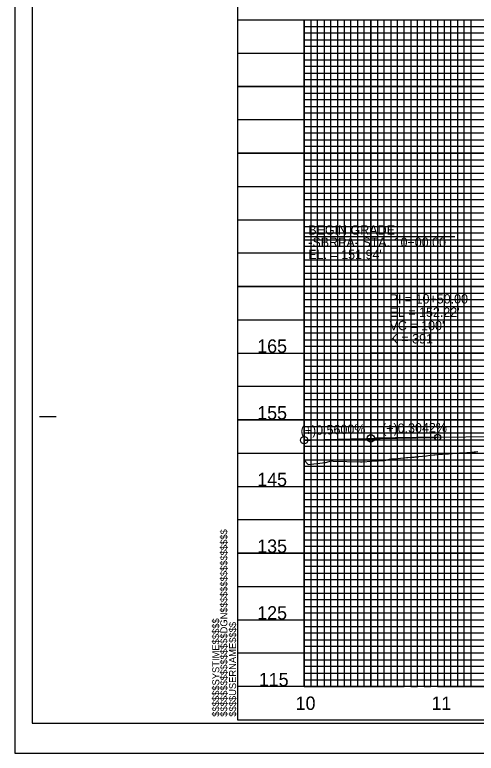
# Model space of a CAD drawing. Extents: x 573468 to 580768, y -57414 to -51768.
# Drawn here: x 578678 to 579024, y -57414 to -56860 of the extents above; entities that cross this region are included whole.
import ezdxf

# ---------------------------------------------------------------- set-up
doc = ezdxf.new("R2010")
doc.units = 0
for name, color, linetype in [('Exist Vertical Profile Ground Line', 7, 'Continuous'), ('Exist Vertical Profile Horizontal Axis Label Major', 7, 'Continuous'), ('Exist Vertical Profile Vertical Axis Label', 7, 'Continuous'), ('Prop Grid Mask', 7, 'Continuous'), ('Prop PFL Text', 7, 'Continuous'), ('Prop Vertical Profile Curve Label', 7, 'Continuous'), ('Prop Vertical Profile Grade', 7, 'Continuous'), ('Prop Vertical Profile Grade Label', 7, 'Continuous'), ('Prop VPI Label', 7, 'Continuous'), ('Sheet Cutting Line CELL', 7, 'Continuous'), ('Sheet DOT Grid CELL', 7, 'Continuous'), ('Sheet Layout Profile Border Port 2', 7, 'Continuous'), ('Sheet Plot Border Inside CELL', 7, 'Continuous'), ('Sheet Plot Border Outside CELL', 7, 'Continuous'), ('Sheet Profile CELL', 7, 'Continuous'), ('Sheet Profile Grid Major CELL', 7, 'Continuous'), ('Sheet Profile Grid Middle CELL', 7, 'Continuous'), ('Sheet Profile Grid Minor CELL', 7, 'Continuous')]:
    doc.layers.add(name, color=color, linetype=linetype)

msp = doc.modelspace()

# ---------------------------------------------------------------- linework, layer by layer
at = {"layer": 'Exist Vertical Profile Ground Line'}
msp.add_lwpolyline([(578895.21, -57193.93), (578898.19, -57197.05), (578911.11, -57195.47), (578915.67, -57194.34), (578916.92, -57194.57), (578937.43, -57195.09), (578938.61, -57195.11), (578945.89, -57194.47), (578948.08, -57194.36), (578950.84, -57194.22), (578953.61, -57194.09), (578955.14, -57194.02), (578956.37, -57193.76), (578959.14, -57193.17), (578960.91, -57192.8), (578961.9, -57192.71), (578964.67, -57192.46), (578967.44, -57192.22), (578970.2, -57191.99), (578971.95, -57191.84), (578972.97, -57191.78), (578975.73, -57191.61), (578977.55, -57191.51), (578978.5, -57191.42), (578980.65, -57191.21), (578981.26, -57191.14), (578984.03, -57190.81), (578986.79, -57190.5), (578989.56, -57190.19), (578992.32, -57189.88), (578993.03, -57189.81), (578995.09, -57189.57), (578995.4, -57189.54), (578997.85, -57189.38), (578998.82, -57189.29), (579000.62, -57189.17), (579003.39, -57188.99), (579006.15, -57188.81), (579008.92, -57188.64), (579010.26, -57188.55), (579011.68, -57188.44), (579014.45, -57188.22), (579017.21, -57188.01), (579019.98, -57187.81), (579022.74, -57187.61), (579023.6, -57187.55), (579025.51, -57187.41)], dxfattribs=at)
at = {"layer": 'Prop Grid Mask'}
msp.add_lwpolyline([(578945.21, -57063.55), (579045.21, -57063.55), (579045.21, -57113.55), (578945.21, -57113.55)], close=True, dxfattribs=at)
at = {"layer": 'Prop PFL Text'}
for q in [(579008.22, -57026.03), (578895.21, -57178.85)]:
    msp.add_line((578895.21, -57026.03), q, dxfattribs=at)
at = {"layer": 'Prop Vertical Profile Curve Label'}
msp.add_circle((578995.21, -57176.69), 2.25, dxfattribs=at)
at = {"layer": 'Prop Vertical Profile Grade'}
msp.add_line((578995.21, -57176.69), (579065.21, -57175.62), dxfattribs=at)
msp.add_spline([(578895.21, -57178.85), (578897.21, -57178.79), (578899.21, -57178.74), (578901.21, -57178.68), (578903.21, -57178.63), (578905.21, -57178.58), (578907.21, -57178.52), (578909.21, -57178.47), (578911.21, -57178.42), (578913.21, -57178.37), (578915.21, -57178.32), (578917.21, -57178.26), (578919.21, -57178.21), (578921.21, -57178.16), (578923.21, -57178.12), (578925.21, -57178.07), (578927.21, -57178.02), (578929.21, -57177.97), (578931.21, -57177.92), (578933.21, -57177.88), (578935.21, -57177.83), (578937.21, -57177.79), (578939.21, -57177.74), (578941.21, -57177.7), (578943.21, -57177.65), (578945.21, -57177.61), (578947.21, -57177.57), (578949.21, -57177.52), (578951.21, -57177.48), (578953.21, -57177.44), (578955.21, -57177.4), (578957.21, -57177.36), (578959.21, -57177.32), (578961.21, -57177.28), (578963.21, -57177.24), (578965.21, -57177.2), (578967.21, -57177.17), (578969.21, -57177.13), (578971.21, -57177.09), (578973.21, -57177.05), (578975.21, -57177.02), (578977.21, -57176.98), (578979.21, -57176.95), (578981.21, -57176.91), (578983.21, -57176.88), (578985.21, -57176.85), (578987.21, -57176.81), (578989.21, -57176.78), (578991.21, -57176.75), (578993.21, -57176.72), (578995.21, -57176.69)], degree=3, dxfattribs=at)
at = {"layer": 'Prop VPI Label'}
for p, q in [((578895.21, -57178.85), (578942.47, -57177.53)), ((578995.21, -57176.69), (578947.96, -57177.41))]:
    msp.add_line(p, q, dxfattribs=at)
for centre in [(578895.21, -57178.85), (578945.21, -57177.45)]:
    msp.add_circle(centre, 2.75, dxfattribs=at)
at = {"layer": 'Sheet Cutting Line CELL'}
for p, q in [((578678.21, -56313.55), (578678.21, -57413.55)), ((578678.21, -57413.55), (580362.21, -57413.55))]:
    msp.add_line(p, q, dxfattribs=at)
at = {"layer": 'Sheet DOT Grid CELL'}
for p, q in [((578845.21, -56863.55), (580345.1, -56863.55)), ((578895.21, -56863.55), (578895.21, -57363.55)), ((578945.21, -56863.55), (578945.21, -57363.55)), ((578995.21, -56863.55), (578995.21, -57363.55)), ((578845.21, -56913.55), (580345.1, -56913.55)), ((578845.21, -56963.55), (580345.1, -56963.55)), ((578845.21, -57013.55), (580345.1, -57013.55)), ((578845.21, -57063.55), (580345.1, -57063.55)), ((578845.21, -57113.55), (580345.1, -57113.55)), ((578845.21, -57163.55), (580345.1, -57163.55)), ((578845.21, -57213.55), (580345.1, -57213.55)), ((578845.21, -57263.55), (580345.1, -57263.55)), ((578845.21, -57313.55), (580345.1, -57313.55))]:
    msp.add_line(p, q, dxfattribs=at)
at = {"layer": 'Sheet Layout Profile Border Port 2'}
msp.add_lwpolyline([(578895.21, -56863.55), (580295.21, -56863.55), (580295.21, -57363.55), (578895.21, -57363.55)], close=True, dxfattribs=at)
at = {"layer": 'Sheet Plot Border Inside CELL'}
msp.add_lwpolyline([(578691.21, -57391.1), (580357.71, -57391.1), (580357.71, -56336), (578691.21, -56336)], close=True, dxfattribs=at)
at = {"layer": 'Sheet Plot Border Outside CELL'}
msp.add_lwpolyline([(578678.21, -57413.55), (580362.21, -57413.55), (580362.21, -56313.55), (578678.21, -56313.55)], close=True, dxfattribs=at)
at = {"layer": 'Sheet Profile CELL'}
for p, q in [((578845.21, -56863.55), (580345.21, -56863.55)), ((578696.71, -57161.05), (578709.21, -57161.05)), ((580345.21, -57363.55), (578845.21, -57363.55)), ((578845.21, -57388.55), (580345.21, -57388.55)), ((578845.21, -57388.55), (578845.21, -57388.55)), ((578845.21, -57388.55), (578845.21, -57388.55)), ((578845.21, -57388.55), (578845.21, -57388.55)), ((578845.21, -57388.55), (578845.21, -57388.55)), ((578845.21, -57388.55), (578845.21, -57388.55)), ((578845.21, -57388.55), (578845.21, -57388.55)), ((578845.21, -57388.55), (578845.21, -57388.55))]:
    msp.add_line(p, q, dxfattribs=at)
msp.add_lwpolyline([(580345.21, -56338.55), (578845.21, -56338.55), (578845.21, -57388.55), (580345.21, -57388.55)], close=True, dxfattribs=at)
msp.add_lwpolyline([(578882.71, -57388.55), (578882.71, -57388.55)], dxfattribs=at)
at = {"layer": 'Sheet Profile Grid Major CELL'}
msp.add_line((578845.21, -57363.55), (578845.21, -57363.55), dxfattribs=at)
for points in [[(578895.21, -56863.55), (578895.21, -57363.55), (578945.21, -57363.55), (578945.21, -56863.55), (578995.21, -56863.55), (578995.21, -57363.55), (579045.21, -57363.55), (579045.21, -56863.55), (579095.21, -56863.55), (579095.21, -57363.55), (579145.21, -57363.55), (579145.21, -56863.55), (579195.21, -56863.55), (579195.21, -57363.55), (579245.21, -57363.55), (579245.21, -56863.55), (579295.21, -56863.55), (579295.21, -57363.55), (579345.21, -57363.55)], [(580345.21, -56913.55), (578845.21, -56913.55)], [(580345.21, -56963.55), (578845.21, -56963.55), (578845.21, -57013.55), (580345.21, -57013.55)], [(580345.21, -57063.55), (578845.21, -57063.55), (578845.21, -57113.55), (580345.21, -57113.55)], [(580345.21, -57163.55), (578845.21, -57163.55), (578845.21, -57213.55), (580345.21, -57213.55)], [(580345.21, -57263.55), (578845.21, -57263.55), (578845.21, -57263.55), (578845.21, -57313.55), (580345.21, -57313.55)], [(580345.21, -57363.55), (578845.21, -57363.55)]]:
    msp.add_lwpolyline(points, dxfattribs=at)
at = {"layer": 'Sheet Profile Grid Middle CELL'}
for points in [[(578870.21, -56863.55), (578920.21, -56863.55), (578920.21, -57363.55), (578970.21, -57363.55), (578970.21, -56863.55), (579020.21, -56863.55), (579020.21, -57363.55), (579070.21, -57363.55), (579070.21, -56863.55), (579120.21, -56863.55), (579120.21, -57363.55), (579170.21, -57363.55), (579170.21, -56863.55), (579220.21, -56863.55), (579220.21, -57363.55), (579270.21, -57363.55), (579270.21, -56863.55), (579320.21, -56863.55), (579320.21, -57363.55), (579370.21, -57363.55)], [(578845.21, -56888.55), (580345.21, -56888.55)], [(580345.21, -56938.55), (578845.21, -56938.55), (578845.21, -56988.55), (580345.21, -56988.55)], [(580345.21, -57038.55), (578845.21, -57038.55), (578845.21, -57088.55), (580345.21, -57088.55)], [(580345.21, -57138.55), (578845.21, -57138.55), (578845.21, -57188.55), (580345.21, -57188.55)], [(580345.21, -57238.55), (578845.21, -57238.55), (578845.21, -57288.55), (580345.21, -57288.55)], [(580345.21, -57338.55), (578845.21, -57338.55)]]:
    msp.add_lwpolyline(points, dxfattribs=at)
at = {"layer": 'Sheet Profile Grid Minor CELL'}
for p, q in [((578895.21, -56868.55), (580295.21, -56868.55)), ((580295.21, -56873.55), (578895.21, -56873.55)), ((578895.21, -56878.55), (580295.21, -56878.55)), ((580295.21, -56883.55), (578895.21, -56883.55)), ((578895.21, -56893.55), (580295.21, -56893.55)), ((580295.21, -56898.55), (578895.21, -56898.55)), ((578895.21, -56903.55), (580295.21, -56903.55)), ((580295.21, -56908.55), (578895.21, -56908.55)), ((578895.21, -56918.55), (580295.21, -56918.55)), ((580295.21, -56923.55), (578895.21, -56923.55)), ((578895.21, -56928.55), (580295.21, -56928.55)), ((580295.21, -56933.55), (578895.21, -56933.55)), ((578895.21, -56943.55), (580295.21, -56943.55)), ((580295.21, -56948.55), (578895.21, -56948.55)), ((578895.21, -56953.55), (580295.21, -56953.55)), ((580295.21, -56958.55), (578895.21, -56958.55)), ((578895.21, -56968.55), (580295.21, -56968.55)), ((580295.21, -56973.55), (578895.21, -56973.55)), ((578895.21, -56978.55), (580295.21, -56978.55)), ((580295.21, -56983.55), (578895.21, -56983.55)), ((578895.21, -56993.55), (580295.21, -56993.55)), ((580295.21, -56998.55), (578895.21, -56998.55)), ((578895.21, -57003.55), (580295.21, -57003.55)), ((580295.21, -57008.55), (578895.21, -57008.55)), ((578895.21, -57018.55), (580295.21, -57018.55)), ((580295.21, -57023.55), (578895.21, -57023.55)), ((578895.21, -57028.55), (580295.21, -57028.55)), ((580295.21, -57033.55), (578895.21, -57033.55)), ((578895.21, -57043.55), (580295.21, -57043.55)), ((580295.21, -57048.55), (578895.21, -57048.55)), ((578895.21, -57053.55), (580295.21, -57053.55)), ((580295.21, -57058.55), (578895.21, -57058.4)), ((578895.21, -57068.55), (580295.21, -57068.55)), ((580295.21, -57073.55), (578895.21, -57073.55)), ((578895.21, -57078.55), (580295.21, -57078.55)), ((580295.21, -57083.55), (578895.21, -57083.55)), ((578895.21, -57093.55), (580295.21, -57093.55)), ((580295.21, -57098.55), (578895.21, -57098.55)), ((578895.21, -57103.55), (580295.21, -57103.55)), ((580295.21, -57108.55), (578895.21, -57108.55)), ((578895.21, -57118.55), (580295.21, -57118.55)), ((580295.21, -57123.55), (578895.21, -57123.55)), ((578895.21, -57128.55), (580295.21, -57128.55)), ((580295.21, -57133.55), (578895.21, -57133.55)), ((578895.21, -57143.55), (580295.21, -57143.55)), ((580295.21, -57148.55), (578895.21, -57148.55)), ((578895.21, -57153.55), (580295.21, -57153.55)), ((580295.21, -57158.55), (578895.21, -57158.55)), ((578895.21, -57168.55), (580295.21, -57168.55)), ((580295.21, -57173.55), (578895.21, -57173.55)), ((578895.21, -57178.55), (580295.21, -57178.55)), ((580295.21, -57183.55), (578895.21, -57183.55)), ((578895.21, -57193.55), (580295.21, -57193.55)), ((580295.21, -57198.55), (578895.21, -57198.55)), ((578895.21, -57203.55), (580295.21, -57203.55)), ((580295.21, -57208.55), (578895.21, -57208.55)), ((578895.21, -57218.55), (580295.21, -57218.55)), ((580295.21, -57223.55), (578895.21, -57223.55)), ((578895.21, -57228.55), (580295.21, -57228.55)), ((580295.21, -57233.55), (578895.21, -57233.55)), ((578895.21, -57243.55), (580295.21, -57243.55)), ((580295.21, -57248.55), (578895.21, -57248.55)), ((578895.21, -57253.55), (580295.21, -57253.55)), ((580295.21, -57258.55), (578895.21, -57258.55)), ((578895.21, -57268.55), (580295.21, -57268.55)), ((580295.21, -57273.55), (578895.21, -57273.55)), ((578895.21, -57278.55), (580295.21, -57278.55)), ((580295.21, -57283.55), (578895.21, -57283.55)), ((578895.21, -57293.55), (580295.21, -57293.55)), ((580295.21, -57298.55), (578895.21, -57298.55)), ((578895.21, -57303.55), (580295.21, -57303.55)), ((580295.21, -57308.55), (578895.21, -57308.55)), ((578895.21, -57318.55), (580295.21, -57318.55)), ((580295.21, -57323.55), (578895.21, -57323.55)), ((578895.21, -57328.55), (580295.21, -57328.55)), ((580295.21, -57333.55), (578895.21, -57333.55)), ((578895.21, -57343.55), (580295.21, -57343.55)), ((580295.21, -57348.55), (578895.21, -57348.55)), ((578895.21, -57353.55), (580295.21, -57353.55)), ((578895.21, -57358.55), (580295.21, -57358.55))]:
    msp.add_line(p, q, dxfattribs=at)
for points in [[(578895.21, -56863.55), (578900.21, -56863.55), (578900.21, -57363.55), (578905.21, -57363.55), (578905.21, -56863.55), (578910.21, -56863.55), (578910.21, -57363.55), (578915.21, -57363.55), (578915.21, -56863.55), (578925.21, -56863.55), (578925.21, -57363.55), (578930.21, -57363.55), (578930.21, -56863.55), (578935.21, -56863.55), (578935.21, -57363.55), (578940.21, -57363.55), (578950.21, -57363.55), (578955.21, -57363.55), (578955.21, -56863.55), (578960.21, -56863.55), (578960.21, -57363.55), (578965.21, -57363.55), (578965.21, -56863.55), (578975.21, -56863.55), (578975.21, -57363.55), (578980.21, -57363.55), (578980.21, -56863.55), (578985.21, -56863.55), (578985.21, -57363.55), (578990.21, -57363.55), (578990.21, -56863.55), (579000.21, -56863.55), (579000.21, -57363.55), (579005.21, -57363.55), (579005.21, -56863.55), (579010.21, -56863.55), (579010.21, -57363.55), (579015.21, -57363.55), (579015.21, -56863.55), (579025.21, -56863.55)], [(578940.21, -57363.55), (578940.21, -56863.55), (578950.21, -56863.55), (578950.21, -57363.55)]]:
    msp.add_lwpolyline(points, dxfattribs=at)

# ---------------------------------------------------------------- texts
at = {"layer": 'Exist Vertical Profile Horizontal Axis Label Major'}
for s, p in [('10', (578888.8, -57381.05)), ('11', (578990.64, -57381.05))]:
    msp.add_text(s, height=10, dxfattribs=at).set_placement(p)
at = {"layer": 'Exist Vertical Profile Vertical Axis Label'}
for s, p in [('165', (578860, -57113.3)), ('155', (578860, -57163.3)), ('145', (578860, -57213.3)), ('135', (578860, -57263.3)), ('125', (578860, -57313.3)), ('115', (578861.2, -57363.3))]:
    msp.add_text(s, height=10, dxfattribs=at).set_placement(p)
at = {"layer": 'Prop PFL Text'}
for s, p in [('BEGIN GRADE', (578898.26, -57024.75)), ('-SBRPA- STA. 10+00.00', (578898.26, -57033.93)), ("EL. = 151.94'", (578898.26, -57043.1))]:
    msp.add_text(s, height=7, dxfattribs=at).set_placement(p)
at = {"layer": 'Prop Vertical Profile Curve Label'}
for s, p in [("VC = 100'", (578959.21, -57096.37)), ('K = 391', (578959.21, -57106.3))]:
    msp.add_text(s, height=7, dxfattribs=at).set_placement(p)
at = {"layer": 'Prop Vertical Profile Grade Label'}
for s, rotation, p in [('(+)0.5600%', 1.6039, (578892.57, -57175.15)), ('(+)0.3042%', 0.8713, (578953.64, -57173.53))]:
    msp.add_text(s, height=7, rotation=rotation, dxfattribs=at).set_placement(p)
at = {"layer": 'Prop VPI Label'}
for s, p in [('PI = 10+50.00', (578959.21, -57076.37)), ("EL = 152.22'", (578959.21, -57086.37))]:
    msp.add_text(s, height=7, dxfattribs=at).set_placement(p)
at = {"layer": 'Sheet Profile CELL'}
for s, p in [('$$$$$$$$$$$$$$$$DGN$$$$$$$$$$$$$$$$', (578837.58, -57386.17)), ('$$$$$$SYSTIME$$$$$', (578831.53, -57386.17)), ('$$$$USERNAME$$$$', (578844.15, -57386.16))]:
    msp.add_text(s, height=5.25, rotation=90, dxfattribs=at).set_placement(p)

doc.saveas('drawing.dxf')
